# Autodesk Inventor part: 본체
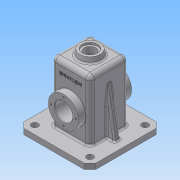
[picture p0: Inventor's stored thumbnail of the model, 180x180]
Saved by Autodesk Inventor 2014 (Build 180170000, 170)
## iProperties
Created: 2016-02
Part Number: 본체
Material: Generic
Document SubType Name: Modeling
Designer: User
Density: 1 g/cm^3
Appearance: Default
Author: User
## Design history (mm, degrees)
sketch "스케치1"
  geometry: L1 (35, 35)-(-35, 35); L2 (-35, 35)-(-35, -35); L3 (-35, -35)-(35, -35); L4 (35, -35)-(35, 35); L5 (-35, 35)-(35, -35); 2 further points
  constraints: 10 end point, 2 parallel, 1 coincident, 1 horizontal, 1 midpoint, 1 perpendicular
  dimensions: "d0" = 70 distance of L1.start L1.end; "d1" = 70 distance of L1.end L2.end
extrude "돌출1" new body sketch "스케치1" distance "d2" = 120; taper "d3" = 0 deg
feature "쉘1" dims "d4" = 5
sketch "스케치3"
  geometry: L1 (-35, 35)-(35, 35) reference; L2 (-35, -35)-(-35, 35) reference; L3 (35, -35)-(-35, -35) reference; L4 (35, 35)-(35, -35) reference; L5 (-65, 65)-(65, 65); L6 (65, 65)-(65, -65); L7 (65, -65)-(-65, -65); L8 (-65, -65)-(-65, 65); L9 (-65, 65)-(65, -65); 2 further points
  constraints: 10 end point, 2 parallel, 1 coincident, 1 horizontal, 1 midpoint, 1 perpendicular
  dimensions: "d5" = 130 distance of L5.start L5.end; "d6" = 130 distance of L5.end L6.end
extrude "돌출2" join sketch "스케치3" distance "d7" = 10; taper "d8" = 0 deg
fillet "모깎기1" dims "d9" = 8
sketch "스케치5"
  geometry: L1 (30, 0)-(30, 115) reference; L2 (30, 115)-(-30, 115) reference; L3 (-30, 115)-(-30, 0) reference; L4 (-30, 0)-(-65, 0) reference; L5 (-65, 0)-(-65, 10) reference; L6 (-65, 10)-(-35, 10) reference; L7 (-35, 10)-(-35, 120) reference; L8 (-35, 120)-(35, 120) reference; L9 (35, 120)-(35, 10) reference; L10 (35, 10)-(65, 10) reference; L11 (65, 10)-(65, 0) reference; L12 (65, 0)-(30, 0) reference; L13 (0, 120)-(-20, 120); L14 (-20, 120)-(-20, 130); L15 (-18.237, 130)-(0, 130); L16 (0, 130)-(0, 120); L17 (-20, 120)-(-18.237, 130); 1 further point
  constraints: 10 end point, 2 parallel, 1 horizontal, 1 midpoint, 1 perpendicular
  dimensions: "d20" = 40 diameter of L13.end L16; "d21" = 10 deg angle of L14 L17; "d22" = 10 distance between parallel lines of L13 L15
revolve "회전1" sketch "스케치5" stored, may be unused: angle "d23" = 90 deg
sketch "스케치6"
  geometry: C1 r 18.237 at (0, 0) reference
hole "구멍1" sketch "스케치6" at (0, 0) diameter "d24" = 21; stored, may be unused: countersink angle "d28" = 90 deg, drill point angle "d30" = 0 deg; dims "d25" = 6, "d26" = 28, "d27" = 4, "d29" = 30
sketch "스케치7"
  geometry: L1 (0, -110)-(54, -110) reference; L2 (27, -120)-(27, -65); C1 r 27.5 at (27, -65)
  constraints: 2 end point, 1 centre point, 1 coincident, 1 perpendicular
  dimensions: "d31" = 55 distance of L2.start L2.end; "d32" = 55 diameter of C1
extrude "돌출3" join sketch "스케치7" distance "d33" = 13; taper "d34" = 0 deg
sketch "스케치8"
  geometry: L1 (-30, 115)-(-30, 0) reference; L2 (-30, 0)-(-65, 0) reference; L3 (-65, 0)-(-65, 10) reference; L4 (-65, 10)-(-35, 10) reference; L5 (-35, 10)-(-35, 27.5) reference; L6 (-35, 27.5)-(-48, 27.5) reference; L7 (-48, 27.5)-(-48, 82.5) reference; L8 (-48, 82.5)-(-35, 82.5) reference; L9 (-35, 82.5)-(-35, 120) reference; L10 (-35, 120)-(-20, 120) reference; L11 (-20, 120)-(-18.237, 130) reference; L12 (-18.237, 130)-(-14, 130) reference; L13 (-14, 130)-(-14, 126) reference; L14 (-14, 126)-(-10.5, 126) reference; L15 (-10.5, 126)-(-10.5, 115) reference; L16 (-10.5, 115)-(-30, 115) reference; L17 (30, 0)-(30, 115) reference; L18 (30, 115)-(10.5, 115) reference; L19 (10.5, 115)-(10.5, 126) reference; L20 (10.5, 126)-(14, 126) reference; L21 (14, 126)-(14, 130) reference; L22 (14, 130)-(18.237, 130) reference; L23 (18.237, 130)-(20, 120) reference; L24 (20, 120)-(35, 120) reference; L25 (35, 120)-(35, 10) reference; L26 (35, 10)-(65, 10) reference; L27 (65, 10)-(65, 0) reference; L28 (65, 0)-(30, 0) reference; L29 (-35, 82.5)-(-30, 82.5); L30 (-30, 82.5)-(-23, 75.5); L31 (-23, 75.5)-(-23, 55); L32 (-48, 82.5)-(-48, 27.5) reference; L33 (-48, 55)-(-23, 55); 1 further point
  constraints: 8 end point, 2 parallel, 1 midpoint, 1 perpendicular, 1 point on line
  dimensions: "d35" = 135 deg angle of L1 L30; "d36" = 7 distance between parallel lines of L1 L31
revolve "회전2" sketch "스케치8" stored, may be unused: angle "d37" = 90 deg
sketch "스케치9"
  geometry: C1 r 27.5 at (0, 0) reference; 1 further point
hole "구멍2" sketch "스케치9" at (0, 0) diameter "d38" = 32; stored, may be unused: countersink angle "d42" = 90 deg, drill point angle "d44" = 0 deg; dims "d39" = 6, "d40" = 4, "d41" = 2, "d43" = 8
sketch "스케치10" dims "d45" = 45
  geometry: C1 r 16 at (0, 0) reference; C2 r 27.5 at (0, 0) reference; 3 further points
  constraints: 2 vertical alignment, 1 coincident, 2 other
hole "구멍3" sketch "스케치10" at (0, -22.5) diameter "d46" = 3.242; stored, may be unused: countersink angle "d50" = 82 deg, drill point angle "d52" = 118 deg; dims "d47" = 8, "d48" = 3.023, "d49" = 2, "d51" = 10
sketch "스케치12"
  geometry: L1 (-30, 115)-(-30, 0) reference; L2 (-30, 0)-(-65, 0) reference; L3 (-65, 0)-(-65, 10) reference; L4 (-65, 10)-(-35, 10) reference; L5 (-35, 10)-(-35, 120) reference; L6 (-35, 120)-(-20, 120) reference; L7 (-20, 120)-(-18.237, 130) reference; L8 (-18.237, 130)-(-14, 130) reference; L9 (-14, 130)-(-14, 126) reference; L10 (-14, 126)-(-10.5, 126) reference; L11 (-10.5, 126)-(-10.5, 115) reference; L12 (-10.5, 115)-(-30, 115) reference; L13 (30, 0)-(30, 115) reference; L14 (30, 115)-(10.5, 115) reference; L15 (10.5, 115)-(10.5, 126) reference; L16 (10.5, 126)-(14, 126) reference; L17 (14, 126)-(14, 130) reference; L18 (14, 130)-(18.237, 130) reference; L19 (18.237, 130)-(20, 120) reference; L20 (20, 120)-(35, 120) reference; L21 (35, 120)-(35, 10) reference; L22 (35, 10)-(65, 10) reference; L23 (65, 10)-(65, 0) reference; L24 (65, 0)-(30, 0) reference; L25 (65, 10)-(-65, 10) reference; L26 (-50, 10)-(-35, 95.069); 1 further point
  constraints: 2 end point, 2 point on line
  dimensions: "d56" = 10 deg angle of L5 L26; "d57" = 15 horizontal distance of L26.start L2.end
feature "리브1" sketch "스케치12" dims "d58" = 1, "d59" = 10, "d60" = 0, "d61" = 0, "d62" = 1, "d63" = 1
chamfer "모따기1" distance "d64" = 10; stored, may be unused: second distance "d65" = 2, angle "d66" = 45 deg
sketch "스케치13"
  geometry: L1 (-65, 55)-(-65, -55) reference; L2 (55, 65)-(-55, 65) reference; C1 r 6 at (-50, 50); 1 further point
  constraints: 1 centre point
  dimensions: "d67" = 15 distance from line of L1 C1.centre; "d68" = 15 distance from line of L2 C1.centre; "d69" = 12 diameter of C1
extrude "돌출4" cut sketch "스케치13" stored distance "d70" = 13; taper "d71" = 0 deg
fillet "모깎기2" dims "d78" = 8
fillet "모깎기3" dims "d79" = 3
chamfer "모따기2" distance "d80" = 1; stored, may be unused: second distance "d81" = 2, angle "d82" = 45 deg
fillet "모깎기5" dims "d84" = 3
fillet "모깎기7" dims "d86" = 0.5
sketch "스케치16"
  geometry: L1 (3.462, -3.306)-(50.538, -3.306); L2 (50.538, -3.306)-(50.538, -20.694); L3 (50.538, -20.694)-(3.462, -20.694); L4 (3.462, -20.694)-(3.462, -3.306); L5 (3.462, -12)-(50.538, -12); L6 (27, -3.306)-(27, -20.694); L7 (62, -99)-(62, 0) reference; L8 (45.237, 18)-(8.763, 18) reference; 1 further point
  constraints: 4 end point, 4 midpoint, 2 other
  dimensions: "d87" = 35 distance between parallel lines of L7 L6; "d88" = 30 distance between parallel lines of L8 L5
feature "엠보싱1" sketch "스케치16" dims "d0" = 70, "d1" = 70, "d8" = 0, "d89" = 0.5, "d90" = 0
node "솔리드1"
mirror "대칭1"
pattern_circular "원형 패턴1" dims angle "d54" = 360 deg
mirror "대칭2"
mirror "대칭3"
pattern_linear "직사각형 패턴1" dims "d74" = 100
pattern_linear "직사각형 패턴2"
node "절단 모서리 투영1"
node "절단 모서리 투영2"
node "절단 모서리 투영3"
